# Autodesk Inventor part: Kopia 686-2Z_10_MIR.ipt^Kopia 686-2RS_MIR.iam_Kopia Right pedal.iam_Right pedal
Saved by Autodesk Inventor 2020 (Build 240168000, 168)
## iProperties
Created: 2017-10
Part Number: Kopia 686-2Z_10_MIR.ipt^Kopia 686-2RS_MIR.iam_Kopia Right pedal.iam_Right pedal
Material: Ogólny
Document SubType Name: Modeling
Designer: Tomasz
Density: 1 g/cm^3
Appearance: Domyślna
Sending System: SolidWorks 2017
Last Author: Tomasz
Last Saved: 2017-10-01
Author: Tomasz
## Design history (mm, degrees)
